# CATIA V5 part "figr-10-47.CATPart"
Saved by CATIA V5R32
Part number: Part1
Bounding box of the stored display mesh (mm): x 0 to 149.165, y -56.328 to 246, z -79.956 to 99.365
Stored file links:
  D:\PROJECTS\Project 2022\CATIA V5 6R 2022\Resources\Part Files\c10_catia_v5_6r2022_prt\c10_catia_v5_6r2022_prt\figr-10-47.CATPart
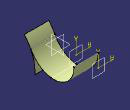
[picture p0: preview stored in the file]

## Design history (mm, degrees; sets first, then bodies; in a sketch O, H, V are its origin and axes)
Body1 (main body)
  Sketch1 on yz-plane, origin (0, 0, 0), H (0, 1, 0), V (0, 0, 1)
    arc A1 centre (-231.2925, -65.467) radius 240.3792 from (-56.3278, 99.3648) to (8.6496, -79.9559) cw
    coincidence: A1 O
  Extrude1: Element1 Sketch1, Lim1 149, Lim2 0
  Sketch2 on zx-plane, origin (0, 0, 0), H (-1, 0, 0), V (0, 0, 1)
    line L1 (-147.95, 52.1519) -> (0, 52.1519)
    point P1 (0, 52.1519)
    coincidence: P1 V
    horizontal: L1 H
  Project1: ToProject Sketch2, Support Extrude1
  Plane1: type Offset, RefPlane zx-plane, Offset 110
  Plane2: type Offset, RefPlane Plane1, Offset 136
  Sketch3 on Plane1, origin (0, 110, 0), H (-1, 0, 0), V (0, 0, 1)
    line L1 (-149.1647, -46.834) -> (0, -46.834)
    point P1 (0, -46.834)
    coincidence: P1 V
    horizontal: L1 H
  Sketch4 on Plane2, origin (0, 246, 0), H (-1, 0, 0), V (0, 0, 1)
    line L1 (-148.4227, 79.0713) -> (0, 79.0713)
    point P1 (0, 79.0713)
    coincidence: P1 V
    horizontal: L1 H
  Sweep1: type Conic, Guide ({sweepconicextendedguide Guide Project1, Reference Extrude1, Angle 0}; Sketch3; {sweepconicextendedguide Guide Sketch4, Reference Plane2, Angle 0})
